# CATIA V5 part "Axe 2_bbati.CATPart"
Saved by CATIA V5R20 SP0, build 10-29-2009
Part number: Axe 2_bbati
Bounding box of the stored display mesh (mm): x -10 to 10, y 156.977 to 166.977, z 108.72 to 118.701
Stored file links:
  C:\Users\thinkmotion1\Desktop\Khaled_IAO_Pack2\IAO_2010_1412_jclement\Non_Optimise\Axe 2_bbati.CATPart
  C:\Users\thinkmotion1\Desktop\Khaled_IAO_Pack2\IAO_2010_1412_jclement\Non_Optimise\Synthese IAO_2.CATProduct
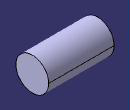
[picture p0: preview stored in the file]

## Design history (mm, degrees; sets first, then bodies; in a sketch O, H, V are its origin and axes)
Set1
  DatumCurve1: linked copy from another document
Body1 (main body)
  Sketch1 on yz-plane, origin (0, 0, 0), H (0, 1, 0), V (0, 0, 1)
    circle A1 centre (161.9769, 113.7106) radius 5
    reference projected circle E1 centre (161.9769, 113.7106) radius 5 from edge of DatumCurve1
    coincidence: A1 E1
  Pad1: profile Sketch1, direction (1, 0, 0), length 10, mirrored extent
